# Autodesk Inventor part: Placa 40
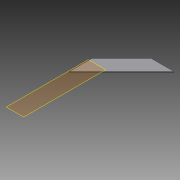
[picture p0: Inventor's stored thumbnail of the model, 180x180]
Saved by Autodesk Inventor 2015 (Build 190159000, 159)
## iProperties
Created: 2015-04
Part Number: Placa 40
Material: Generic
Document SubType Name: Modeling
Designer: suporte
Density: 1 g/cm^3
Appearance: Default
Author: suporte
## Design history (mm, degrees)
workplane "Work Plane1"
sketch "Sketch1"
  geometry: L1 (68.082, 375.157)-(-81.918, 225.262) reference; L2 (-81.918, 437.32)-(-81.918, -481.238) reference; L3 (199.719, 718.762)-(-81.918, 437.32) reference; L4 (299.719, 718.762)-(818.318, 718.762) reference; L5 (411.925, 718.762)-(-81.918, 225.262); L6 (-81.918, 225.262)-(-81.918, 437.32); L7 (-81.918, 437.32)-(199.719, 718.762); L8 (199.719, 718.762)-(411.925, 718.762); 1 further point
  constraints: 8 end point, 2 collinear, 1 parallel, 1 perpendicular, 1 point on line
extrude "Extrusion1" new body sketch "Sketch1" distance "d0" = 12.5; taper "d1" = 0 deg
body "Solid1"
node "Reference1"
node "Reference2"
node "Reference3"
node "Reference4"
